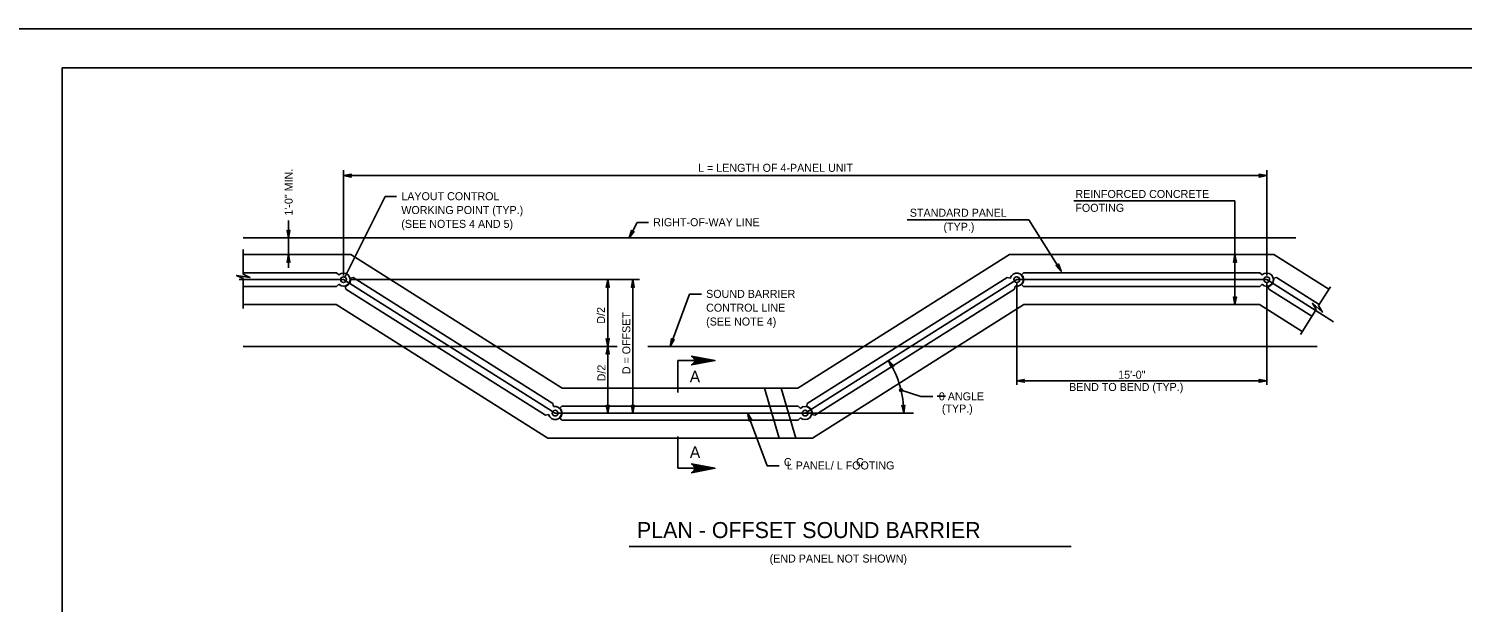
# Model space of a CAD drawing. Extents: x 3385 to 6532, y -616 to 1166.
# Drawn here: x 5470 to 6021, y 946 to 1166 of the extents above; entities that cross this region are included whole.
import ezdxf

# ---------------------------------------------------------------- set-up
doc = ezdxf.new("R2010")
doc.units = 0
for name, color, linetype in [('1', 7, 'Continuous'), ('2', 7, 'Continuous'), ('PLT-BNDY', 7, 'Continuous')]:
    doc.layers.add(name, color=color, linetype=linetype)

msp = doc.modelspace()

# ---------------------------------------------------------------- linework, layer by layer
at = {"layer": '1'}
for p, q in [((5591.32, 1111.35), (5591.32, 1070.97)), ((5591.32, 1109.28), (5945.74, 1109.28)), ((5945.74, 1111.35), (5945.74, 1070.97)), ((5591.81, 1070.34), (5607.3, 1101.28)), ((5607.3, 1101.28), (5611.7, 1101.28)), ((5871.66, 1099.66), (5933.53, 1099.66)), ((5933.53, 1099.66), (5933.53, 1059.76)), ((5570.19, 1092.12), (5570.19, 1073.9)), ((5701.03, 1085.36), (5704, 1091.29)), ((5704, 1091.29), (5708.4, 1091.29)), ((5807.67, 1092.35), (5854.46, 1092.35)), ((5854.46, 1092.35), (5866.86, 1072.56)), ((5552.78, 1085.36), (5956.86, 1085.36)), ((5552.78, 1080.96), (5552.78, 1071.5)), ((5552.78, 1078.96), (5594.09, 1078.96)), ((5594.09, 1078.96), (5675.3, 1027.76)), ((5765.76, 1027.76), (5846.96, 1078.96)), ((5846.96, 1078.96), (5948.51, 1078.96)), ((5948.51, 1078.96), (5969.59, 1065.67)), ((5551.3, 1069.36), (5591.32, 1069.36)), ((5552.78, 1072.03), (5588.65, 1072.03)), ((5552.78, 1069.74), (5552.78, 1058.25)), ((5588.65, 1072.03), (5589.53, 1071.15)), ((5591.32, 1069.36), (5672.53, 1018.16)), ((5593.87, 1069.36), (5704.91, 1069.36)), ((5593.92, 1069.95), (5595, 1070.2)), ((5595, 1070.2), (5671.69, 1021.84)), ((5692.77, 1069.36), (5692.77, 1018.16)), ((5702.37, 1069.36), (5702.37, 1018.16)), ((5768.53, 1018.16), (5849.74, 1069.36)), ((5769.36, 1021.84), (5846.06, 1070.2)), ((5846.06, 1070.2), (5847.27, 1069.92)), ((5849.74, 1069.36), (5945.74, 1069.36)), ((5849.74, 1068.26), (5849.74, 1028.98)), ((5851.62, 1071.25), (5852.4, 1072.03)), ((5852.4, 1072.03), (5943.07, 1072.03)), ((5943.07, 1072.03), (5943.95, 1071.15)), ((5945.74, 1069.36), (5971.36, 1053.21)), ((5945.74, 1068.26), (5945.74, 1028.98)), ((5948.34, 1069.95), (5949.42, 1070.2)), ((5949.42, 1070.2), (5965.89, 1059.81)), ((5552.78, 1066.7), (5588.65, 1066.7)), ((5588.65, 1066.7), (5589.53, 1067.57)), ((5591.91, 1066.76), (5592.15, 1065.68)), ((5592.15, 1065.68), (5668.85, 1017.33)), ((5724.17, 1063.8), (5716.74, 1043.76)), ((5724.17, 1063.8), (5728.71, 1063.8)), ((5772.21, 1017.33), (5848.9, 1065.68)), ((5848.9, 1065.68), (5849.18, 1066.89)), ((5851.62, 1067.48), (5852.4, 1066.7)), ((5852.4, 1066.7), (5943.07, 1066.7)), ((5943.07, 1066.7), (5943.95, 1067.57)), ((5946.33, 1066.76), (5946.57, 1065.68)), ((5946.57, 1065.68), (5963.05, 1055.29)), ((5970.19, 1066.62), (5965.65, 1059.42)), ((5552.78, 1059.76), (5588.55, 1059.76)), ((5588.55, 1059.76), (5669.75, 1008.56)), ((5771.3, 1008.56), (5852.51, 1059.76)), ((5852.51, 1059.76), (5942.96, 1059.76)), ((5942.96, 1059.76), (5959.35, 1049.43)), ((5964.71, 1057.92), (5958.68, 1048.36)), ((5552.78, 1043.76), (5696.39, 1043.76)), ((5708.17, 1043.76), (5965.07, 1043.76)), ((5719.65, 1026.04), (5719.65, 1038.3)), ((5719.65, 1038.3), (5733.91, 1038.3)), ((5849.74, 1030.53), (5945.74, 1030.53)), ((5675.3, 1027.76), (5765.76, 1027.76)), ((5752.96, 1027.76), (5758.51, 1008.56)), ((5764.91, 1008.56), (5759.36, 1027.76)), ((5812.96, 1024.45), (5805.33, 1026.9)), ((5812.96, 1024.45), (5817.5, 1024.45)), ((5822.46, 1024.58), (5819.27, 1024.58)), ((5671.69, 1021.84), (5671.97, 1020.63)), ((5672.53, 1018.16), (5810.18, 1018.16)), ((5674.41, 1020.05), (5675.19, 1020.83)), ((5675.19, 1020.83), (5765.86, 1020.83)), ((5746.46, 1018.16), (5753.96, 997.93)), ((5765.86, 1020.83), (5766.74, 1019.95)), ((5769.12, 1020.76), (5769.36, 1021.84)), ((5668.85, 1017.33), (5670.06, 1017.6)), ((5674.41, 1016.28), (5675.19, 1015.49)), ((5675.19, 1015.49), (5765.86, 1015.49)), ((5765.86, 1015.49), (5766.74, 1016.37)), ((5771.13, 1017.57), (5772.21, 1017.33)), ((5669.75, 1008.56), (5771.3, 1008.56)), ((5719.65, 996.94), (5719.65, 1009.21)), ((5719.65, 996.94), (5733.91, 996.94)), ((5753.96, 997.93), (5758.51, 997.93)), ((5701.03, 966.95), (5870.67, 966.95))]:
    msp.add_line(p, q, dxfattribs=at)
for points in [[(5591.32, 1109.28), (5594.3, 1109.84), (5594.07, 1109.68), (5593.95, 1109.48), (5593.92, 1109.28), (5593.95, 1109.08), (5594.07, 1108.88), (5594.3, 1108.72), (5591.32, 1109.28), (5594.07, 1108.88), (5593.95, 1109.08), (5591.32, 1109.28), (5593.92, 1109.28), (5593.95, 1109.48), (5591.32, 1109.28), (5594.07, 1109.68)], [(5945.74, 1109.28), (5942.76, 1108.72), (5942.98, 1108.88), (5943.1, 1109.08), (5943.14, 1109.28), (5943.1, 1109.48), (5942.98, 1109.68), (5942.76, 1109.84), (5945.74, 1109.28), (5942.98, 1109.68), (5943.1, 1109.48), (5945.74, 1109.28), (5943.14, 1109.28), (5943.1, 1109.08), (5945.74, 1109.28), (5942.98, 1108.88)], [(5570.19, 1085.36), (5569.63, 1088.35), (5569.71, 1088.23), (5569.79, 1088.12), (5569.89, 1088.06), (5569.99, 1088), (5570.09, 1087.98), (5570.19, 1087.96), (5570.29, 1087.98), (5570.39, 1088), (5570.49, 1088.06), (5570.59, 1088.12), (5570.67, 1088.23), (5570.75, 1088.35), (5570.19, 1085.36), (5570.67, 1088.23), (5570.59, 1088.12), (5570.19, 1085.36), (5570.49, 1088.06), (5570.39, 1088), (5570.19, 1085.36), (5570.29, 1087.98), (5570.19, 1087.96), (5570.19, 1085.36), (5570.09, 1087.98), (5569.99, 1088), (5570.19, 1085.36), (5569.89, 1088.06), (5569.79, 1088.12), (5570.19, 1085.36), (5569.71, 1088.23)], [(5701.03, 1085.36), (5701.87, 1088.28), (5701.89, 1088.14), (5701.91, 1088), (5701.97, 1087.91), (5702.03, 1087.81), (5702.12, 1087.75), (5702.2, 1087.69), (5702.29, 1087.66), (5702.39, 1087.63), (5702.51, 1087.64), (5702.62, 1087.64), (5702.75, 1087.71), (5702.87, 1087.78), (5701.03, 1085.36), (5702.75, 1087.71), (5702.62, 1087.64), (5701.03, 1085.36), (5702.51, 1087.64), (5702.39, 1087.63), (5701.03, 1085.36), (5702.29, 1087.66), (5702.2, 1087.69), (5701.03, 1085.36), (5702.12, 1087.75), (5702.03, 1087.81), (5701.03, 1085.36), (5701.97, 1087.91), (5701.91, 1088), (5701.03, 1085.36), (5701.89, 1088.14)], [(5570.19, 1078.96), (5570.75, 1075.98), (5570.67, 1076.09), (5570.59, 1076.21), (5570.49, 1076.27), (5570.39, 1076.33), (5570.29, 1076.35), (5570.19, 1076.36), (5570.09, 1076.35), (5569.99, 1076.33), (5569.89, 1076.27), (5569.79, 1076.21), (5569.71, 1076.09), (5569.63, 1075.98), (5570.19, 1078.96), (5569.71, 1076.09), (5569.79, 1076.21), (5570.19, 1078.96), (5569.89, 1076.27), (5569.99, 1076.33), (5570.19, 1078.96), (5570.09, 1076.35), (5570.19, 1076.36), (5570.19, 1078.96), (5570.29, 1076.35), (5570.39, 1076.33), (5570.19, 1078.96), (5570.49, 1076.27), (5570.59, 1076.21), (5570.19, 1078.96), (5570.67, 1076.09)], [(5933.53, 1078.96), (5934.09, 1075.98), (5933.93, 1076.21), (5933.73, 1076.33), (5933.53, 1076.36), (5933.33, 1076.33), (5933.13, 1076.21), (5932.97, 1075.98), (5933.53, 1078.96), (5933.13, 1076.21), (5933.33, 1076.33), (5933.53, 1078.96), (5933.53, 1076.36), (5933.73, 1076.33), (5933.53, 1078.96), (5933.93, 1076.21)], [(5866.86, 1072.56), (5864.8, 1074.79), (5864.93, 1074.74), (5865.06, 1074.68), (5865.18, 1074.69), (5865.29, 1074.69), (5865.39, 1074.73), (5865.48, 1074.77), (5865.56, 1074.83), (5865.63, 1074.9), (5865.68, 1075), (5865.74, 1075.11), (5865.74, 1075.25), (5865.75, 1075.39), (5866.86, 1072.56), (5865.74, 1075.25), (5865.74, 1075.11), (5866.86, 1072.56), (5865.68, 1075), (5865.63, 1074.9), (5866.86, 1072.56), (5865.56, 1074.83), (5865.48, 1074.77), (5866.86, 1072.56), (5865.39, 1074.73), (5865.29, 1074.69), (5866.86, 1072.56), (5865.18, 1074.69), (5865.06, 1074.68), (5866.86, 1072.56), (5864.93, 1074.74)], [(5552.78, 1071.5), (5555.37, 1070.23), (5550.29, 1070.92), (5552.78, 1069.74)], [(5692.77, 1069.36), (5693.33, 1066.38), (5693.25, 1066.49), (5693.17, 1066.61), (5693.07, 1066.67), (5692.97, 1066.73), (5692.87, 1066.75), (5692.77, 1066.76), (5692.67, 1066.75), (5692.57, 1066.73), (5692.47, 1066.67), (5692.37, 1066.61), (5692.29, 1066.49), (5692.21, 1066.38), (5692.77, 1069.36), (5692.29, 1066.49), (5692.37, 1066.61), (5692.77, 1069.36), (5692.47, 1066.67), (5692.57, 1066.73), (5692.77, 1069.36), (5692.67, 1066.75), (5692.77, 1066.76), (5692.77, 1069.36), (5692.87, 1066.75), (5692.97, 1066.73), (5692.77, 1069.36), (5693.07, 1066.67), (5693.17, 1066.61), (5692.77, 1069.36), (5693.25, 1066.49)], [(5702.37, 1069.36), (5702.93, 1066.38), (5702.85, 1066.49), (5702.77, 1066.61), (5702.67, 1066.67), (5702.57, 1066.73), (5702.47, 1066.75), (5702.37, 1066.76), (5702.27, 1066.75), (5702.17, 1066.73), (5702.07, 1066.67), (5701.97, 1066.61), (5701.89, 1066.49), (5701.81, 1066.38), (5702.37, 1069.36), (5701.89, 1066.49), (5701.97, 1066.61), (5702.37, 1069.36), (5702.07, 1066.67), (5702.17, 1066.73), (5702.37, 1069.36), (5702.27, 1066.75), (5702.37, 1066.76), (5702.37, 1069.36), (5702.47, 1066.75), (5702.57, 1066.73), (5702.37, 1069.36), (5702.67, 1066.67), (5702.77, 1066.61), (5702.37, 1069.36), (5702.85, 1066.49)], [(5933.53, 1059.76), (5932.97, 1062.74), (5933.13, 1062.52), (5933.33, 1062.4), (5933.53, 1062.36), (5933.73, 1062.4), (5933.93, 1062.52), (5934.09, 1062.74), (5933.53, 1059.76), (5933.93, 1062.52), (5933.73, 1062.4), (5933.53, 1059.76), (5933.53, 1062.36), (5933.33, 1062.4), (5933.53, 1059.76), (5933.13, 1062.52)], [(5965.65, 1059.42), (5967.14, 1056.94), (5963.25, 1060.28), (5964.69, 1057.94)], [(5692.77, 1043.76), (5693.33, 1046.74), (5693.25, 1046.63), (5693.17, 1046.51), (5693.07, 1046.46), (5692.97, 1046.4), (5692.87, 1046.38), (5692.77, 1046.36), (5692.67, 1046.38), (5692.57, 1046.4), (5692.47, 1046.46), (5692.37, 1046.51), (5692.29, 1046.63), (5692.21, 1046.74), (5692.77, 1043.76), (5692.29, 1046.63), (5692.37, 1046.51), (5692.77, 1043.76), (5692.47, 1046.46), (5692.57, 1046.4), (5692.77, 1043.76), (5692.67, 1046.38), (5692.77, 1046.36), (5692.77, 1043.76), (5692.87, 1046.38), (5692.97, 1046.4), (5692.77, 1043.76), (5693.07, 1046.46), (5693.17, 1046.51), (5692.77, 1043.76), (5693.25, 1046.63)], [(5716.74, 1043.76), (5717.26, 1046.75), (5717.32, 1046.48), (5717.47, 1046.3), (5717.65, 1046.2), (5717.85, 1046.16), (5718.07, 1046.2), (5718.3, 1046.36), (5716.74, 1043.76), (5718.07, 1046.2), (5717.85, 1046.16), (5716.74, 1043.76), (5717.65, 1046.2), (5717.47, 1046.3), (5716.74, 1043.76), (5717.32, 1046.48)], [(5692.77, 1043.76), (5693.33, 1040.78), (5693.25, 1040.89), (5693.17, 1041.01), (5693.07, 1041.07), (5692.97, 1041.13), (5692.87, 1041.14), (5692.77, 1041.16), (5692.67, 1041.14), (5692.57, 1041.13), (5692.47, 1041.07), (5692.37, 1041.01), (5692.29, 1040.89), (5692.21, 1040.78), (5692.77, 1043.76), (5692.29, 1040.89), (5692.37, 1041.01), (5692.77, 1043.76), (5692.47, 1041.07), (5692.57, 1041.13), (5692.77, 1043.76), (5692.67, 1041.14), (5692.77, 1041.16), (5692.77, 1043.76), (5692.87, 1041.14), (5692.97, 1041.13), (5692.77, 1043.76), (5693.07, 1041.07), (5693.17, 1041.01), (5692.77, 1043.76), (5693.25, 1040.89)], [(5733.91, 1038.3), (5724.96, 1036.62), (5725.31, 1036.86), (5725.65, 1037.1), (5725.83, 1037.4), (5726.01, 1037.7), (5726.06, 1038), (5726.11, 1038.3), (5726.06, 1038.6), (5726.01, 1038.9), (5725.83, 1039.2), (5725.65, 1039.5), (5725.31, 1039.74), (5724.96, 1039.98), (5733.91, 1038.3), (5725.31, 1039.74), (5725.65, 1039.5), (5733.91, 1038.3), (5725.83, 1039.2), (5726.01, 1038.9), (5733.91, 1038.3), (5726.06, 1038.6), (5726.11, 1038.3), (5733.91, 1038.3), (5726.06, 1038), (5726.01, 1037.7), (5733.91, 1038.3), (5725.83, 1037.4), (5725.65, 1037.1), (5733.91, 1038.3), (5725.31, 1036.86)], [(5800.53, 1038.34), (5802.64, 1036.16), (5802.38, 1036.26), (5802.15, 1036.25), (5801.96, 1036.17), (5801.81, 1036.03), (5801.71, 1035.82), (5801.71, 1035.54), (5800.53, 1038.34), (5801.71, 1035.82), (5801.81, 1036.03), (5800.53, 1038.34), (5801.96, 1036.17), (5802.15, 1036.25), (5800.53, 1038.34), (5802.38, 1036.26)], [(5849.74, 1030.53), (5852.72, 1031.09), (5852.6, 1031.01), (5852.49, 1030.93), (5852.43, 1030.83), (5852.37, 1030.73), (5852.35, 1030.63), (5852.34, 1030.53), (5852.35, 1030.43), (5852.37, 1030.33), (5852.43, 1030.23), (5852.49, 1030.13), (5852.6, 1030.05), (5852.72, 1029.97), (5849.74, 1030.53), (5852.6, 1030.05), (5852.49, 1030.13), (5849.74, 1030.53), (5852.43, 1030.23), (5852.37, 1030.33), (5849.74, 1030.53), (5852.35, 1030.43), (5852.34, 1030.53), (5849.74, 1030.53), (5852.35, 1030.63), (5852.37, 1030.73), (5849.74, 1030.53), (5852.43, 1030.83), (5852.49, 1030.93), (5849.74, 1030.53), (5852.6, 1031.01)], [(5945.74, 1030.53), (5942.76, 1029.97), (5942.87, 1030.05), (5942.98, 1030.13), (5943.04, 1030.23), (5943.1, 1030.33), (5943.12, 1030.43), (5943.14, 1030.53), (5943.12, 1030.63), (5943.1, 1030.73), (5943.04, 1030.83), (5942.98, 1030.93), (5942.87, 1031.01), (5942.76, 1031.09), (5945.74, 1030.53), (5942.87, 1031.01), (5942.98, 1030.93), (5945.74, 1030.53), (5943.04, 1030.83), (5943.1, 1030.73), (5945.74, 1030.53), (5943.12, 1030.63), (5943.14, 1030.53), (5945.74, 1030.53), (5943.12, 1030.43), (5943.1, 1030.33), (5945.74, 1030.53), (5943.04, 1030.23), (5942.98, 1030.13), (5945.74, 1030.53), (5942.87, 1030.05)], [(5692.77, 1018.16), (5692.21, 1021.14), (5692.29, 1021.03), (5692.37, 1020.91), (5692.47, 1020.86), (5692.57, 1020.8), (5692.67, 1020.78), (5692.77, 1020.76), (5692.87, 1020.78), (5692.97, 1020.8), (5693.07, 1020.86), (5693.17, 1020.91), (5693.25, 1021.03), (5693.33, 1021.14), (5692.77, 1018.16), (5693.25, 1021.03), (5693.17, 1020.91), (5692.77, 1018.16), (5693.07, 1020.86), (5692.97, 1020.8), (5692.77, 1018.16), (5692.87, 1020.78), (5692.77, 1020.76), (5692.77, 1018.16), (5692.67, 1020.78), (5692.57, 1020.8), (5692.77, 1018.16), (5692.47, 1020.86), (5692.37, 1020.91), (5692.77, 1018.16), (5692.29, 1021.03)], [(5702.37, 1018.16), (5701.81, 1021.14), (5701.89, 1021.03), (5701.97, 1020.91), (5702.07, 1020.86), (5702.17, 1020.8), (5702.27, 1020.78), (5702.37, 1020.76), (5702.47, 1020.78), (5702.57, 1020.8), (5702.67, 1020.86), (5702.77, 1020.91), (5702.85, 1021.03), (5702.93, 1021.14), (5702.37, 1018.16), (5702.85, 1021.03), (5702.77, 1020.91), (5702.37, 1018.16), (5702.67, 1020.86), (5702.57, 1020.8), (5702.37, 1018.16), (5702.47, 1020.78), (5702.37, 1020.76), (5702.37, 1018.16), (5702.27, 1020.78), (5702.17, 1020.8), (5702.37, 1018.16), (5702.07, 1020.86), (5701.97, 1020.91), (5702.37, 1018.16), (5701.89, 1021.03)], [(5746.46, 1018.16), (5748.03, 1015.56), (5747.8, 1015.72), (5747.57, 1015.76), (5747.37, 1015.72), (5747.19, 1015.62), (5747.05, 1015.44), (5746.98, 1015.17), (5746.46, 1018.16), (5747.05, 1015.44), (5747.19, 1015.62), (5746.46, 1018.16), (5747.37, 1015.72), (5747.57, 1015.76), (5746.46, 1018.16), (5747.8, 1015.72)], [(5806.36, 1018.16), (5805.71, 1021.13), (5805.87, 1020.9), (5806.08, 1020.79), (5806.28, 1020.76), (5806.48, 1020.8), (5806.67, 1020.93), (5806.83, 1021.16), (5806.36, 1018.16), (5806.67, 1020.93), (5806.48, 1020.8), (5806.36, 1018.16), (5806.28, 1020.76), (5806.08, 1020.79), (5806.36, 1018.16), (5805.87, 1020.9)], [(5733.91, 996.94), (5724.96, 995.26), (5725.31, 995.5), (5725.65, 995.74), (5725.83, 996.04), (5726.01, 996.34), (5726.06, 996.64), (5726.11, 996.94), (5726.06, 997.24), (5726.01, 997.54), (5725.83, 997.84), (5725.65, 998.14), (5725.31, 998.38), (5724.96, 998.62), (5733.91, 996.94), (5725.31, 998.38), (5725.65, 998.14), (5733.91, 996.94), (5725.83, 997.84), (5726.01, 997.54), (5733.91, 996.94), (5726.06, 997.24), (5726.11, 996.94), (5733.91, 996.94), (5726.06, 996.64), (5726.01, 996.34), (5733.91, 996.94), (5725.83, 996.04), (5725.65, 995.74), (5733.91, 996.94), (5725.31, 995.5)]]:
    msp.add_lwpolyline(points, dxfattribs=at)
for centre, radius in [((5591.32, 1069.36), 1.1), ((5849.74, 1069.36), 1.1), ((5945.74, 1069.36), 1.1), ((5805.33, 1026.9), 0.533), ((5805.33, 1026.9), 0.267), ((5672.53, 1018.16), 1.1), ((5768.53, 1018.16), 1.1)]:
    msp.add_circle(centre, radius, dxfattribs=at)
for centre, radius, start, end in [((5591.32, 1069.36), 2.53, 225, 135), ((5591.32, 1069.36), 2.67, 282.7683, 12.7708), ((5849.74, 1069.36), 2.53, 257.231, 167.231), ((5849.74, 1069.36), 2.67, 314.9993, 45.0018), ((5945.74, 1069.36), 2.53, 225, 135), ((5945.74, 1069.36), 2.67, 282.7683, 12.7708), ((5768.53, 1018.16), 37.83, 0, 32.2309), ((5672.53, 1018.16), 2.53, 192.769, 102.769), ((5672.53, 1018.16), 2.67, 314.9982, 45.0007), ((5768.53, 1018.16), 2.53, 225, 135), ((5768.53, 1018.16), 2.67, 347.2292, 77.2317)]:
    msp.add_arc(centre, radius, start, end, dxfattribs=at)
at = {"layer": '2'}
for p, q in [((5483.34, 586.69), (5483.34, 1150.69)), ((5483.34, 1150.69), (6269.34, 1150.69))]:
    msp.add_line(p, q, dxfattribs=at)
at = {"layer": 'PLT-BNDY'}
msp.add_lwpolyline([(5443.34, 1165.69), (6284.34, 1165.69), (6284.34, 571.69), (5443.34, 571.69)], close=True, dxfattribs=at)

# ---------------------------------------------------------------- texts
at = {"layer": '1'}
for s, height, p in [('L = LENGTH OF 4-PANEL UNIT', 3.0721, (5727.44, 1110.75)), ('LAYOUT CONTROL', 3.0721, (5613.51, 1099.85)), ('REINFORCED CONCRETE ', 3.0721, (5872.27, 1100.71)), ('WORKING POINT (TYP.)', 3.0721, (5613.51, 1094.54)), ('STANDARD PANEL', 3.0721, (5808.72, 1093.51)), ('FOOTING', 3.072, (5872.27, 1095.4)), ('(SEE NOTES 4 AND 5)', 3.0721, (5613.51, 1089.23)), ('RIGHT-OF-WAY LINE', 3.0721, (5710.21, 1089.87)), ('(TYP.)', 3.072, (5821.64, 1088.13)), ('SOUND BARRIER', 3.0721, (5730.52, 1062.37)), ('CONTROL LINE', 3.0721, (5730.52, 1057.06)), ('(SEE NOTE 4)', 3.0721, (5730.52, 1051.75)), ('A', 4.45, (5724.23, 1029.95)), ('BEND TO BEND (TYP.)', 3.0721, (5869.87, 1026.63)), ('15\'-0"', 3.072, (5888.7, 1031.34)), ('0 ANGLE', 3.072, (5819.87, 1023.03)), (' (TYP.)', 3.072, (5819.87, 1018.36)), ('A', 4.45, (5724.28, 1000.93)), ('C', 3.07, (5760.37, 997.8)), ('L PANEL/ L FOOTING', 3.0721, (5761.47, 996.51)), ('C', 3.07, (5788.08, 997.8)), ('PLAN - OFFSET SOUND BARRIER', 6.144, (5703.96, 970.18)), ('(END PANEL NOT SHOWN)', 3.0721, (5754.89, 960.78))]:
    msp.add_text(s, height=height, dxfattribs=at).set_placement(p)
for s, p in [('1\'-0" MIN.', (5571.79, 1093.93)), ('D/2', (5691.7, 1052.45)), ('D = OFFSET', (5701.43, 1033.07)), ('D/2', (5691.86, 1030.32))]:
    msp.add_text(s, height=3.072, rotation=90, dxfattribs=at).set_placement(p)

doc.saveas('drawing.dxf')
